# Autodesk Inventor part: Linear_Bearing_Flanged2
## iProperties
Author: Administrator
Shininess: 20.0
PropertySet Name: _Private Model Information
Created: 2001-02
Part Number: Linear_Bearing_Flanged2
Document SubType Name: Modeling
Designer: Administrator
Control State: 0
Master: False
Checked Out: False
PropertySet Name: Design Tracking Control
Density: 0.0
Volumn: 0.0
Area: 0.0
PropertySet Name: Model Information
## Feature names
1. Extrusion1
2. RoundFlange [Extrusion]
3. RoundFillet [Fillet]
4. SquareFlange [Extrusion]
5. SquareFillet [Fillet]
6. Hole1
7. MiddleDoubleCyl [Extrusion]
8. Fillet2
9. MiddleFlangeFillet [Fillet]
